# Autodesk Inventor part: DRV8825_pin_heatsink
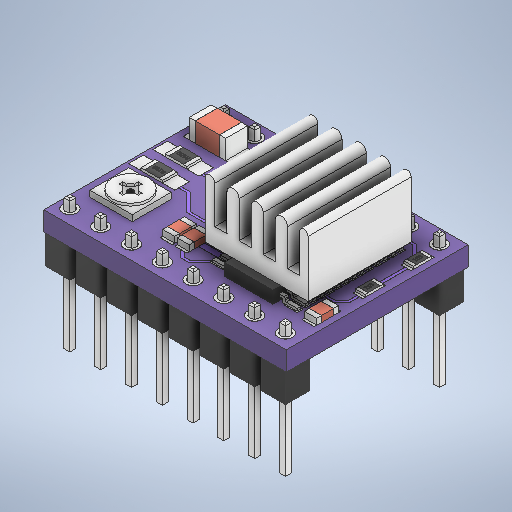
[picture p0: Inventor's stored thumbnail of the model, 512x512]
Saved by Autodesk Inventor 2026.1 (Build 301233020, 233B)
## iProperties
Created: 2025-12
Part Number: DRV8825_pin_heatsink
Material: Generic
Document SubType Name: Modeling
Designer: hp
Density: 1 g/cm^3
Appearance: Default
Title: DRV8825_pin_heatsink.stp
Author: quang
Sending System: Autodesk Inventor 2024
Preprocessor: ST-DEVELOPER v20
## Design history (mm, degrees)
feature "Solid1"
feature "Solid2:1"
feature "Solid2:2"
feature "Solid2:3"
feature "Solid2:4"
feature "Solid2:5"
feature "Solid2:6"
feature "Solid2:7"
feature "Solid2:8"
feature "Solid2:9"
feature "Solid2:10"
feature "Solid2:11"
feature "Solid2:12"
feature "Solid2:13"
feature "Solid2:14"
feature "Solid2:15"
feature "Solid3:1"
feature "Solid4:1"
feature "Solid4:2"
feature "Solid4:3"
feature "Solid4:4"
feature "Solid4:5"
feature "Solid4:6"
feature "Solid4:7"
feature "Solid4:8"
feature "Solid4:9"
feature "Solid4:10"
feature "Solid4:11"
feature "Solid4:12"
feature "Solid4:13"
feature "Solid4:14"
feature "Solid4:15"
feature "Solid4:16"
feature "Solid5:1"
feature "Solid5:2"
feature "Solid5:3"
feature "Solid5:4"
feature "Solid5:5"
feature "Solid5:6"
feature "Solid5:7"
feature "Solid5:8"
feature "Solid5:9"
feature "Solid5:10"
feature "Solid5:11"
feature "Solid5:12"
feature "Solid5:13"
feature "Solid5:14"
feature "Solid5:15"
feature "Solid5:16"
body "Solid2"
body "Solid3"
body "Solid4"
body "Solid5"
body "Solid6"
body "Solid7"
body "Solid8"
body "Solid9"
body "Solid10"
body "Solid11"
body "Solid12"
body "Solid13"
body "Solid14"
body "Solid15"
body "Solid16"
body "Solid17"
body "Solid18"
body "Solid19"
body "Solid20"
body "Solid21"
body "Solid22"
body "Solid23"
body "Solid24"
body "Solid25"
body "Solid26"
body "Solid27"
body "Solid28"
body "Solid29"
body "Solid30"
body "Solid31"
body "Solid32"
body "Solid33"
body "Solid34"
body "Solid35"
body "Solid36"
body "Solid37"
body "Solid38"
body "Solid39"
body "Solid40"
body "Solid41"
body "Solid42"
body "Solid43"
body "Solid44"
body "Solid45"
body "Solid46"
body "Solid47"
body "Solid48"
body "Solid49"
body "Solid50"
